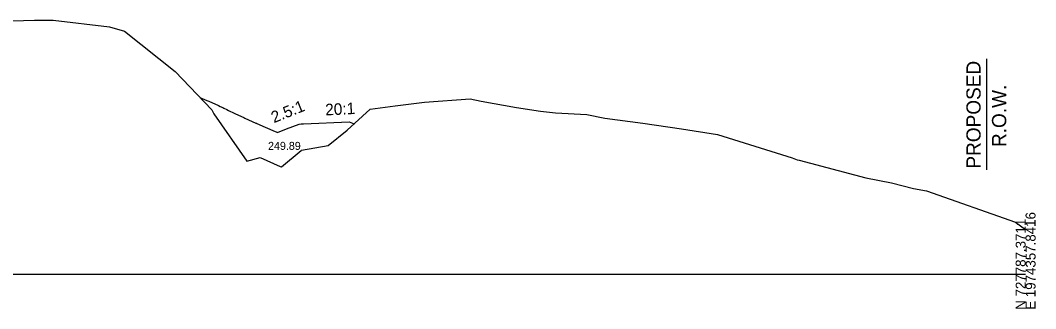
# Model space of a CAD drawing. Extents: x -26 to 1604, y -13 to 9623.
# Drawn here: x 317.3 to 602.8, y 4990.3 to 5071.4 of the extents above; entities that cross this region are included whole.
import ezdxf

# ---------------------------------------------------------------- set-up
doc = ezdxf.new("R2010")
doc.units = 0
for name, color, linetype in [('DTM CONTOURS_MAJOR', 7, 'Continuous'), ('DTM_X_GROUND', 7, 'Continuous'), ('XS_CELL', 7, 'Continuous'), ('XS_P_GROUND', 7, 'Continuous'), ('XS_P_ROW', 7, 'Continuous'), ('XS_P_TX_DCH', 7, 'Continuous'), ('XS_P_TX_FS_BS', 7, 'Continuous')]:
    doc.layers.add(name, color=color, linetype=linetype)

msp = doc.modelspace()

# ---------------------------------------------------------------- linework, layer by layer
at = {"layer": 'DTM_X_GROUND'}
msp.add_lwpolyline([(312.01, 5071.23), (321.32, 5071.43), (326.54, 5071.42), (342.36, 5069.6), (346.62, 5068.41), (360.82, 5057.02), (371.18, 5046.24), (371.73, 5045.14), (381.01, 5031.77), (384.75, 5032.83), (390.42, 5030.3), (390.71, 5030.23), (396.32, 5034.83), (396.42, 5034.86), (403.83, 5036.21), (409.26, 5040.48), (415.73, 5046.41), (422.68, 5047.39), (431, 5048.41), (443.76, 5049.38), (446.94, 5048.72), (456.8, 5046.92), (463.62, 5045.86), (467.81, 5045.44), (476.61, 5044.95), (481.71, 5043.89), (492.35, 5042.48), (503.21, 5040.93), (513.37, 5039.33), (534.37, 5032.74), (535.73, 5032.18), (536.29, 5032.09), (555.04, 5027.15), (562.31, 5025.72), (568.48, 5024.09), (572.18, 5023.47), (597.12, 5014.64), (600, 5012.55)], dxfattribs=at)
at = {"layer": 'XS_CELL'}
msp.add_line((100, 5000), (600, 5000), dxfattribs=at)
at = {"layer": 'XS_P_GROUND'}
for points in [[(367.83, 5049.73), (369.75, 5048.88), (370.28, 5048.64), (373.02, 5047.42), (373.49, 5047.21), (374.25, 5046.87), (374.55, 5046.68), (375.34, 5046.33), (375.8, 5046.05), (377.44, 5045.31), (377.83, 5045.08), (380.15, 5044.04), (380.41, 5043.9), (383.56, 5042.51), (383.69, 5042.46), (383.8, 5042.41), (386.2, 5041.34), (388.98, 5040.16), (389.28, 5040.03), (389.65, 5039.89)], [(389.65, 5039.89), (392.14, 5040.86), (395.71, 5042.25), (396.32, 5042.28), (396.93, 5042.3), (409.79, 5042.89), (409.81, 5042.88), (410.73, 5042.52), (411.19, 5042.33), (411.25, 5042.31)]]:
    msp.add_lwpolyline(points, dxfattribs=at)
at = {"layer": 'XS_P_ROW'}
msp.add_line((589, 5060.63), (589, 5029.37), dxfattribs=at)

# ---------------------------------------------------------------- texts
at = {"layer": 'DTM CONTOURS_MAJOR'}
for p in [(409.75, 5042.83), (383.52, 5042.45), (389.61, 5039.83), (389.61, 5039.83), (395.67, 5042.19), (411.21, 5042.25)]:
    msp.add_text('X', height=0.12, dxfattribs=at).set_placement(p)
at = {"layer": 'XS_CELL'}
for s, p in [('E 1974357.8416', (602.8, 4990)), ('N 727787.3711', (600, 4990))]:
    msp.add_text(s, height=2.8, rotation=90, dxfattribs=at).set_placement(p)
at = {"layer": 'XS_P_ROW'}
for s, p in [('PROPOSED', (587.35, 5029.71)), ('R.O.W.', (594.55, 5035.78))]:
    msp.add_text(s, height=4, rotation=90, dxfattribs=at).set_placement(p)
at = {"layer": 'XS_P_TX_DCH'}
msp.add_text('249.89', height=2.25, dxfattribs=at).set_placement((386.96, 5034.98))
at = {"layer": 'XS_P_TX_FS_BS'}
for s, rotation, p in [('2.5:1', 21.8014, (388.62, 5042.48)), ('20:1', 2.8624, (403.12, 5044.66))]:
    msp.add_text(s, height=3.24, rotation=rotation, dxfattribs=at).set_placement(p)

doc.saveas('drawing.dxf')
